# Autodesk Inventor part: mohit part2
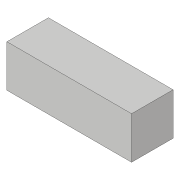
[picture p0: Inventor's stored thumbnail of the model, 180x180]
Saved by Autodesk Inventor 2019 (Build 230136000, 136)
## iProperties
Created: 2020-02
Part Number: mohit part2
Material: Generic
Document SubType Name: Modeling
Designer: Mahabaleshwarppa
Density: 1 g/cm^3
Appearance: Default
Author: Mahabaleshwarppa
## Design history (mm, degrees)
sketch "Sketch1"
  geometry: L1 (0, 0)-(-15.014, 0); L2 (-15.014, 0)-(-15.014, 5.063); L3 (-15.014, 5.063)-(0, 5.063); L4 (0, 5.063)-(0, 0)
  constraints: 8 end point, 2 parallel, 1 horizontal, 1 perpendicular
extrude "Extrusion1" new body sketch "Sketch1" distance "d0" = 5; taper "d1" = 0 deg
body "Solid1"
